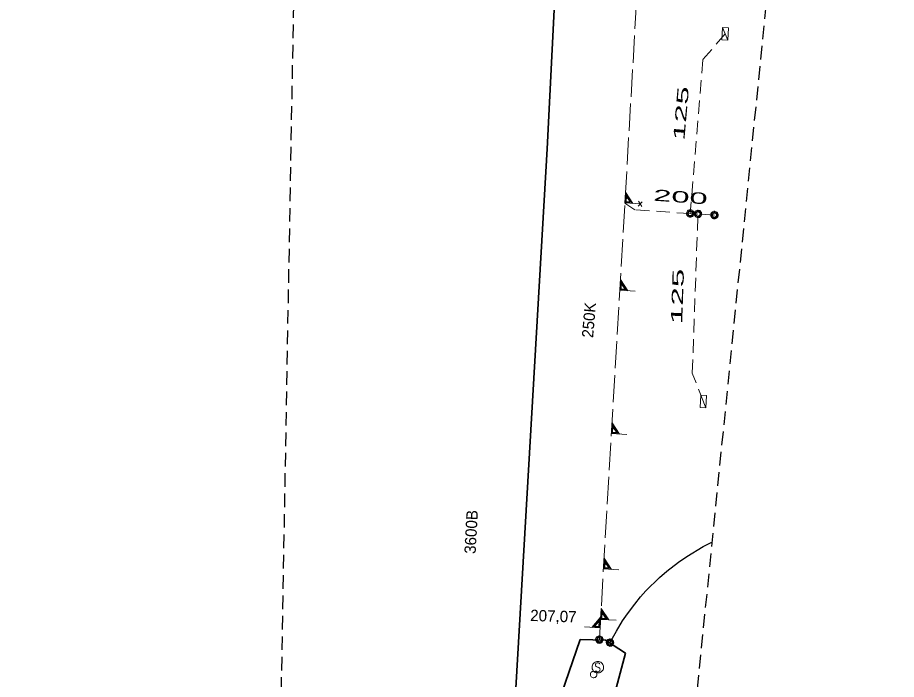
# Model space of a CAD drawing. Extents: x -744446 to -743929, y -1041261 to -1040599.
# Drawn here: x -744445.1 to -744383.1, y -1040917.5 to -1040870.7 of the extents above; entities that cross this region are included whole.
import ezdxf

# ---------------------------------------------------------------- set-up
doc = ezdxf.new("R2010")
doc.units = 0
doc.header["$LTSCALE"] = 0.32
doc.linetypes.add('LONG_DASHED', pattern=[7.5, 6, -1.5])
doc.linetypes.add('MEDIUM_DASHED', pattern=[4.5, 3, -1.5])
for name, color, linetype, lineweight in [('1', 7, 'MEDIUM_DASHED', 25), ('18', 7, 'Continuous', 13), ('20', 7, 'LONG_DASHED', 13), ('49', 7, 'MEDIUM_DASHED', 13)]:
    doc.layers.add(name, color=color, linetype=linetype, lineweight=lineweight)

msp = doc.modelspace()

# ---------------------------------------------------------------- linework, layer by layer
at = {"layer": '1'}
msp.add_lwpolyline([(-744438.077, -1041259.731), (-744438.679, -1041250.888), (-744445.125, -1041198.426), (-744434.434, -1041080.103), (-744426.87, -1040938.41), (-744425.446, -1040859.072), (-744414.192, -1040822.094), (-744390.076, -1040771.45), (-744357.118, -1040726.434), (-744307.278, -1040693.475), (-744241.36, -1040670.967), (-743937.498, -1040598.618), (-743928.655, -1040619.519), (-744129.684, -1040665.585), (-744218.109, -1040687.29), (-744311.358, -1040718.641), (-744361.198, -1040777.323), (-744391.745, -1040864.141), (-744411.355, -1041059.185), (-744416.379, -1041145.154), (-744432.569, -1041193.163), (-744432.047, -1041202.053), (-744422.803, -1041230.992), (-744424.813, -1041260.936)], close=True, dxfattribs=at)
at = {"layer": '18'}
for p, q in [((-744395.376, -1040871.437), (-744395.011, -1040872.332)), ((-744401.045, -1040883.732), (-744401.334, -1040884.051)), ((-744401.077, -1040884.069), (-744401.299, -1040883.684)), ((-744396.919, -1040897.398), (-744396.549, -1040898.291))]:
    msp.add_line(p, q, dxfattribs=at)
for points in [[(-744394.965, -1040871.455), (-744395.011, -1040872.328), (-744395.422, -1040872.306), (-744395.376, -1040871.433)], [(-744397.393, -1040884.557), (-744397.399, -1040884.501), (-744397.416, -1040884.448), (-744397.445, -1040884.399), (-744397.483, -1040884.358), (-744397.529, -1040884.326), (-744397.581, -1040884.304), (-744397.636, -1040884.293), (-744397.692, -1040884.295), (-744397.747, -1040884.308), (-744397.798, -1040884.333), (-744397.842, -1040884.368), (-744397.878, -1040884.411), (-744397.903, -1040884.461), (-744397.918, -1040884.516), (-744397.921, -1040884.572), (-744397.912, -1040884.627), (-744397.891, -1040884.68), (-744397.86, -1040884.726), (-744397.82, -1040884.765), (-744397.772, -1040884.795), (-744397.719, -1040884.814), (-744397.663, -1040884.821), (-744397.607, -1040884.817), (-744397.553, -1040884.8), (-744397.504, -1040884.773), (-744397.462, -1040884.735), (-744397.429, -1040884.69), (-744397.406, -1040884.639), (-744397.394, -1040884.584)], [(-744397.452, -1040884.56), (-744397.458, -1040884.511), (-744397.476, -1040884.465), (-744397.504, -1040884.424), (-744397.541, -1040884.391), (-744397.585, -1040884.369), (-744397.633, -1040884.357), (-744397.682, -1040884.357), (-744397.73, -1040884.369), (-744397.774, -1040884.392), (-744397.811, -1040884.425), (-744397.839, -1040884.466), (-744397.856, -1040884.513), (-744397.862, -1040884.562), (-744397.855, -1040884.611), (-744397.837, -1040884.657), (-744397.809, -1040884.697), (-744397.772, -1040884.73), (-744397.728, -1040884.752), (-744397.679, -1040884.764), (-744397.63, -1040884.763), (-744397.582, -1040884.751), (-744397.539, -1040884.727), (-744397.502, -1040884.694), (-744397.474, -1040884.653), (-744397.458, -1040884.606)], [(-744397.511, -1040884.564), (-744397.517, -1040884.522), (-744397.534, -1040884.484), (-744397.562, -1040884.453), (-744397.597, -1040884.43), (-744397.637, -1040884.419), (-744397.679, -1040884.419), (-744397.719, -1040884.431), (-744397.754, -1040884.454), (-744397.781, -1040884.486), (-744397.798, -1040884.524), (-744397.803, -1040884.565), (-744397.797, -1040884.607), (-744397.779, -1040884.644), (-744397.751, -1040884.676), (-744397.715, -1040884.698), (-744397.675, -1040884.709), (-744397.633, -1040884.708), (-744397.593, -1040884.695), (-744397.559, -1040884.672), (-744397.532, -1040884.639), (-744397.516, -1040884.601)], [(-744396.852, -1040884.593), (-744396.858, -1040884.537), (-744396.875, -1040884.484), (-744396.904, -1040884.435), (-744396.942, -1040884.394), (-744396.988, -1040884.362), (-744397.04, -1040884.34), (-744397.095, -1040884.329), (-744397.151, -1040884.331), (-744397.206, -1040884.344), (-744397.257, -1040884.369), (-744397.301, -1040884.404), (-744397.337, -1040884.447), (-744397.362, -1040884.497), (-744397.377, -1040884.552), (-744397.38, -1040884.608), (-744397.371, -1040884.663), (-744397.35, -1040884.716), (-744397.319, -1040884.762), (-744397.279, -1040884.801), (-744397.231, -1040884.831), (-744397.178, -1040884.85), (-744397.122, -1040884.857), (-744397.066, -1040884.853), (-744397.012, -1040884.836), (-744396.963, -1040884.809), (-744396.921, -1040884.771), (-744396.888, -1040884.726), (-744396.865, -1040884.675), (-744396.853, -1040884.62)], [(-744396.911, -1040884.596), (-744396.917, -1040884.547), (-744396.935, -1040884.501), (-744396.963, -1040884.46), (-744397, -1040884.427), (-744397.044, -1040884.405), (-744397.092, -1040884.393), (-744397.141, -1040884.393), (-744397.189, -1040884.405), (-744397.233, -1040884.428), (-744397.27, -1040884.461), (-744397.298, -1040884.502), (-744397.315, -1040884.549), (-744397.321, -1040884.598), (-744397.314, -1040884.647), (-744397.296, -1040884.693), (-744397.268, -1040884.733), (-744397.231, -1040884.766), (-744397.187, -1040884.788), (-744397.138, -1040884.8), (-744397.089, -1040884.799), (-744397.041, -1040884.787), (-744396.998, -1040884.763), (-744396.961, -1040884.73), (-744396.933, -1040884.689), (-744396.917, -1040884.642)], [(-744396.97, -1040884.6), (-744396.976, -1040884.558), (-744396.993, -1040884.52), (-744397.021, -1040884.489), (-744397.056, -1040884.466), (-744397.096, -1040884.455), (-744397.138, -1040884.455), (-744397.178, -1040884.467), (-744397.213, -1040884.49), (-744397.24, -1040884.522), (-744397.257, -1040884.56), (-744397.262, -1040884.601), (-744397.256, -1040884.643), (-744397.238, -1040884.68), (-744397.21, -1040884.712), (-744397.174, -1040884.734), (-744397.134, -1040884.745), (-744397.092, -1040884.744), (-744397.052, -1040884.731), (-744397.018, -1040884.708), (-744396.991, -1040884.675), (-744396.975, -1040884.637)], [(-744395.685, -1040884.671), (-744395.691, -1040884.615), (-744395.708, -1040884.562), (-744395.737, -1040884.513), (-744395.775, -1040884.472), (-744395.821, -1040884.44), (-744395.873, -1040884.418), (-744395.928, -1040884.407), (-744395.984, -1040884.409), (-744396.039, -1040884.422), (-744396.09, -1040884.447), (-744396.134, -1040884.482), (-744396.17, -1040884.525), (-744396.195, -1040884.575), (-744396.21, -1040884.63), (-744396.213, -1040884.686), (-744396.204, -1040884.741), (-744396.183, -1040884.794), (-744396.152, -1040884.84), (-744396.112, -1040884.879), (-744396.064, -1040884.909), (-744396.011, -1040884.928), (-744395.955, -1040884.935), (-744395.899, -1040884.931), (-744395.845, -1040884.914), (-744395.796, -1040884.887), (-744395.754, -1040884.849), (-744395.721, -1040884.804), (-744395.698, -1040884.753), (-744395.686, -1040884.698)], [(-744395.744, -1040884.674), (-744395.75, -1040884.625), (-744395.768, -1040884.579), (-744395.796, -1040884.538), (-744395.833, -1040884.505), (-744395.877, -1040884.483), (-744395.925, -1040884.471), (-744395.974, -1040884.471), (-744396.022, -1040884.483), (-744396.066, -1040884.506), (-744396.103, -1040884.539), (-744396.131, -1040884.58), (-744396.148, -1040884.627), (-744396.154, -1040884.676), (-744396.147, -1040884.725), (-744396.129, -1040884.771), (-744396.101, -1040884.811), (-744396.064, -1040884.844), (-744396.02, -1040884.866), (-744395.971, -1040884.878), (-744395.922, -1040884.877), (-744395.874, -1040884.865), (-744395.831, -1040884.841), (-744395.794, -1040884.808), (-744395.766, -1040884.767), (-744395.75, -1040884.72)], [(-744395.803, -1040884.678), (-744395.809, -1040884.636), (-744395.826, -1040884.598), (-744395.854, -1040884.567), (-744395.889, -1040884.544), (-744395.929, -1040884.533), (-744395.971, -1040884.533), (-744396.011, -1040884.545), (-744396.046, -1040884.568), (-744396.073, -1040884.6), (-744396.09, -1040884.638), (-744396.095, -1040884.679), (-744396.089, -1040884.721), (-744396.071, -1040884.758), (-744396.043, -1040884.79), (-744396.007, -1040884.812), (-744395.967, -1040884.823), (-744395.925, -1040884.822), (-744395.885, -1040884.809), (-744395.851, -1040884.786), (-744395.824, -1040884.753), (-744395.808, -1040884.715)], [(-744396.507, -1040897.414), (-744396.548, -1040898.287), (-744396.96, -1040898.267), (-744396.919, -1040897.394)], [(-744403.808, -1040914.643), (-744403.814, -1040914.587), (-744403.831, -1040914.534), (-744403.86, -1040914.485), (-744403.898, -1040914.444), (-744403.944, -1040914.412), (-744403.996, -1040914.39), (-744404.051, -1040914.379), (-744404.107, -1040914.381), (-744404.162, -1040914.394), (-744404.213, -1040914.419), (-744404.257, -1040914.454), (-744404.293, -1040914.497), (-744404.318, -1040914.547), (-744404.333, -1040914.602), (-744404.336, -1040914.658), (-744404.327, -1040914.713), (-744404.306, -1040914.766), (-744404.275, -1040914.812), (-744404.235, -1040914.851), (-744404.187, -1040914.881), (-744404.134, -1040914.9), (-744404.078, -1040914.907), (-744404.022, -1040914.903), (-744403.968, -1040914.886), (-744403.919, -1040914.859), (-744403.877, -1040914.821), (-744403.844, -1040914.776), (-744403.821, -1040914.725), (-744403.809, -1040914.67)], [(-744403.867, -1040914.646), (-744403.873, -1040914.597), (-744403.891, -1040914.551), (-744403.919, -1040914.51), (-744403.956, -1040914.477), (-744404, -1040914.455), (-744404.048, -1040914.443), (-744404.097, -1040914.443), (-744404.145, -1040914.455), (-744404.189, -1040914.478), (-744404.226, -1040914.511), (-744404.254, -1040914.552), (-744404.271, -1040914.599), (-744404.277, -1040914.648), (-744404.27, -1040914.697), (-744404.252, -1040914.743), (-744404.224, -1040914.783), (-744404.187, -1040914.816), (-744404.143, -1040914.838), (-744404.094, -1040914.85), (-744404.045, -1040914.849), (-744403.997, -1040914.837), (-744403.954, -1040914.813), (-744403.917, -1040914.78), (-744403.889, -1040914.739), (-744403.873, -1040914.692)], [(-744403.926, -1040914.65), (-744403.932, -1040914.608), (-744403.949, -1040914.57), (-744403.977, -1040914.539), (-744404.012, -1040914.516), (-744404.052, -1040914.505), (-744404.094, -1040914.505), (-744404.134, -1040914.517), (-744404.169, -1040914.54), (-744404.196, -1040914.572), (-744404.213, -1040914.61), (-744404.218, -1040914.651), (-744404.212, -1040914.693), (-744404.194, -1040914.73), (-744404.166, -1040914.762), (-744404.13, -1040914.784), (-744404.09, -1040914.795), (-744404.048, -1040914.794), (-744404.008, -1040914.781), (-744403.974, -1040914.758), (-744403.947, -1040914.725), (-744403.931, -1040914.687)], [(-744403.058, -1040914.852), (-744403.064, -1040914.796), (-744403.081, -1040914.743), (-744403.11, -1040914.694), (-744403.148, -1040914.653), (-744403.194, -1040914.621), (-744403.246, -1040914.599), (-744403.301, -1040914.588), (-744403.357, -1040914.59), (-744403.412, -1040914.603), (-744403.463, -1040914.628), (-744403.507, -1040914.663), (-744403.543, -1040914.706), (-744403.568, -1040914.756), (-744403.583, -1040914.811), (-744403.586, -1040914.867), (-744403.577, -1040914.922), (-744403.556, -1040914.975), (-744403.525, -1040915.021), (-744403.485, -1040915.06), (-744403.437, -1040915.09), (-744403.384, -1040915.109), (-744403.328, -1040915.116), (-744403.272, -1040915.112), (-744403.218, -1040915.095), (-744403.169, -1040915.068), (-744403.127, -1040915.03), (-744403.094, -1040914.985), (-744403.071, -1040914.934), (-744403.059, -1040914.879)], [(-744403.117, -1040914.855), (-744403.123, -1040914.806), (-744403.141, -1040914.76), (-744403.169, -1040914.719), (-744403.206, -1040914.686), (-744403.25, -1040914.664), (-744403.298, -1040914.652), (-744403.347, -1040914.652), (-744403.395, -1040914.664), (-744403.439, -1040914.687), (-744403.476, -1040914.72), (-744403.504, -1040914.761), (-744403.521, -1040914.808), (-744403.527, -1040914.857), (-744403.52, -1040914.906), (-744403.502, -1040914.952), (-744403.474, -1040914.992), (-744403.437, -1040915.025), (-744403.393, -1040915.047), (-744403.344, -1040915.059), (-744403.295, -1040915.058), (-744403.247, -1040915.046), (-744403.204, -1040915.022), (-744403.167, -1040914.989), (-744403.139, -1040914.948), (-744403.123, -1040914.901)], [(-744403.176, -1040914.859), (-744403.182, -1040914.817), (-744403.199, -1040914.779), (-744403.227, -1040914.748), (-744403.262, -1040914.725), (-744403.302, -1040914.714), (-744403.344, -1040914.714), (-744403.384, -1040914.726), (-744403.419, -1040914.749), (-744403.446, -1040914.781), (-744403.463, -1040914.819), (-744403.468, -1040914.86), (-744403.462, -1040914.902), (-744403.444, -1040914.939), (-744403.416, -1040914.971), (-744403.38, -1040914.993), (-744403.34, -1040915.004), (-744403.298, -1040915.003), (-744403.258, -1040914.99), (-744403.224, -1040914.967), (-744403.197, -1040914.934), (-744403.181, -1040914.896)], [(-744403.776, -1040916.592), (-744403.782, -1040916.523), (-744403.8, -1040916.456), (-744403.829, -1040916.392), (-744403.869, -1040916.335), (-744403.918, -1040916.285), (-744403.974, -1040916.244), (-744404.037, -1040916.214), (-744404.104, -1040916.194), (-744404.173, -1040916.187), (-744404.243, -1040916.191), (-744404.31, -1040916.207), (-744404.374, -1040916.235), (-744404.433, -1040916.273), (-744404.484, -1040916.321), (-744404.526, -1040916.376), (-744404.558, -1040916.438), (-744404.579, -1040916.505), (-744404.588, -1040916.574), (-744404.585, -1040916.644), (-744404.57, -1040916.712), (-744404.544, -1040916.776), (-744404.507, -1040916.836), (-744404.461, -1040916.888), (-744404.406, -1040916.931), (-744404.345, -1040916.964), (-744404.279, -1040916.987), (-744404.21, -1040916.997), (-744404.14, -1040916.996), (-744404.072, -1040916.983), (-744404.006, -1040916.958), (-744403.946, -1040916.923), (-744403.893, -1040916.877), (-744403.849, -1040916.824), (-744403.814, -1040916.763), (-744403.79, -1040916.698), (-744403.778, -1040916.629)], [(-744404.245, -1040917.106), (-744404.252, -1040917.054), (-744404.269, -1040917.004), (-744404.298, -1040916.96), (-744404.336, -1040916.923), (-744404.38, -1040916.896), (-744404.431, -1040916.88), (-744404.483, -1040916.875), (-744404.534, -1040916.882), (-744404.583, -1040916.901), (-744404.627, -1040916.931), (-744404.663, -1040916.97), (-744404.689, -1040917.015), (-744404.703, -1040917.066), (-744404.706, -1040917.118), (-744404.698, -1040917.17), (-744404.678, -1040917.218), (-744404.647, -1040917.261), (-744404.608, -1040917.296), (-744404.561, -1040917.32), (-744404.511, -1040917.334), (-744404.458, -1040917.336), (-744404.407, -1040917.326), (-744404.358, -1040917.304), (-744404.316, -1040917.272), (-744404.284, -1040917.232), (-744404.26, -1040917.185), (-744404.247, -1040917.134)]]:
    msp.add_lwpolyline(points, close=True, dxfattribs=at)
for points in [[(-744401.184, -1040883.884), (-744402.277, -1040883.82), (-744402.232, -1040883.052), (-744401.7, -1040883.854)], [(-744401.816, -1040883.797), (-744402.23, -1040883.773), (-744402.197, -1040883.208), (-744401.814, -1040883.797)], [(-744401.896, -1040883.745), (-744402.187, -1040883.728), (-744402.166, -1040883.357), (-744401.896, -1040883.746)], [(-744401.541, -1040890.049), (-744402.635, -1040889.985), (-744402.59, -1040889.217), (-744402.058, -1040890.019)], [(-744402.173, -1040889.962), (-744402.588, -1040889.938), (-744402.555, -1040889.373), (-744402.172, -1040889.962)], [(-744402.254, -1040889.911), (-744402.545, -1040889.894), (-744402.523, -1040889.522), (-744402.254, -1040889.912)], [(-744402.13, -1040900.161), (-744403.224, -1040900.097), (-744403.179, -1040899.329), (-744402.647, -1040900.131)], [(-744402.762, -1040900.074), (-744403.177, -1040900.05), (-744403.144, -1040899.485), (-744402.761, -1040900.074)], [(-744402.843, -1040900.023), (-744403.134, -1040900.006), (-744403.112, -1040899.634), (-744402.843, -1040900.024)], [(-744402.687, -1040909.715), (-744403.781, -1040909.651), (-744403.736, -1040908.883), (-744403.204, -1040909.685)], [(-744403.319, -1040909.628), (-744403.734, -1040909.604), (-744403.701, -1040909.039), (-744403.318, -1040909.628)], [(-744403.4, -1040909.577), (-744403.691, -1040909.56), (-744403.669, -1040909.188), (-744403.4, -1040909.578)], [(-744402.895, -1040913.279), (-744403.989, -1040913.215), (-744403.944, -1040912.447), (-744403.412, -1040913.249)], [(-744403.527, -1040913.192), (-744403.942, -1040913.168), (-744403.909, -1040912.603), (-744403.526, -1040913.192)], [(-744403.608, -1040913.141), (-744403.899, -1040913.124), (-744403.877, -1040912.752), (-744403.608, -1040913.142)], [(-744405.114, -1040913.747), (-744404.02, -1040913.811), (-744403.975, -1040913.041), (-744404.597, -1040913.777)], [(-744404.476, -1040913.733), (-744404.061, -1040913.757), (-744404.028, -1040913.193), (-744404.477, -1040913.733)], [(-744404.389, -1040913.691), (-744404.099, -1040913.708), (-744404.077, -1040913.338), (-744404.389, -1040913.692)], [(-744404.031, -1040916.369), (-744404.053, -1040916.331), (-744404.085, -1040916.301), (-744404.123, -1040916.28), (-744404.166, -1040916.27), (-744404.21, -1040916.272), (-744404.251, -1040916.286), (-744404.287, -1040916.311), (-744404.316, -1040916.344), (-744404.334, -1040916.384), (-744404.34, -1040916.428), (-744404.335, -1040916.471), (-744404.318, -1040916.512), (-744404.291, -1040916.546), (-744404.256, -1040916.572), (-744404.215, -1040916.587), (-744404.171, -1040916.591), (-744404.167, -1040916.591)], [(-744404.332, -1040916.822), (-744404.308, -1040916.859), (-744404.275, -1040916.888), (-744404.235, -1040916.907), (-744404.192, -1040916.915), (-744404.148, -1040916.91), (-744404.107, -1040916.894), (-744404.072, -1040916.868), (-744404.045, -1040916.833), (-744404.028, -1040916.793), (-744404.023, -1040916.749), (-744404.03, -1040916.705), (-744404.048, -1040916.665), (-744404.077, -1040916.632), (-744404.113, -1040916.607), (-744404.155, -1040916.593), (-744404.172, -1040916.591)]]:
    msp.add_lwpolyline(points, dxfattribs=at)
at = {"layer": '18', "lineweight": 35}
msp.add_lwpolyline([(-744405.436, -1040914.627), (-744403.633, -1040914.677), (-744402.237, -1040915.595), (-744403.265, -1040919.486), (-744405.096, -1040919.552), (-744406.737, -1040918.467)], close=True, dxfattribs=at)
at = {"layer": '20'}
msp.add_line((-744404.072, -1040914.656), (-744401.298, -1040867.055), dxfattribs=at)
at = {"layer": '20', "linetype": 'Continuous', "lineweight": 35}
msp.add_lwpolyline([(-744429.62, -1041252.21), (-744428.789, -1041237.94), (-744437.959, -1041195.193), (-744423.3, -1041145.69), (-744417.879, -1041053.98), (-744409.949, -1040917.67), (-744407.76, -1040880.01), (-744407.219, -1040869.23), (-744404.395, -1040847.829), (-744400.25, -1040827.35), (-744393.491, -1040807.621), (-744384.879, -1040787.9), (-744372.238, -1040768.547), (-744361.26, -1040752.62), (-744345.317, -1040736.555), (-744330.739, -1040723.14), (-744312.333, -1040710.859), (-744294.67, -1040700.75), (-744274.728, -1040692.583), (-744254.699, -1040686.49), (-744133.87, -1040657.39), (-743953.289, -1040613.85), (-743946.017, -1040612.141)], dxfattribs=at)
at = {"layer": '20', "lineweight": 25}
msp.add_lwpolyline([(-744403.322, -1040914.865), (-744402.873, -1040914.034), (-744402.431, -1040913.318), (-744402.087, -1040912.814), (-744401.574, -1040912.137), (-744401.162, -1040911.629), (-744400.785, -1040911.198), (-744399.84, -1040910.254), (-744399.3, -1040909.807), (-744398.495, -1040909.183), (-744397.908, -1040908.765), (-744396.745, -1040908.076), (-744396.14, -1040907.765), (-744396.131, -1040907.761)], dxfattribs=at)
at = {"layer": '49'}
for points in [[(-744395.19, -1040871.89), (-744396.763, -1040873.705), (-744397.657, -1040884.57)], [(-744397.657, -1040884.57), (-744401.565, -1040884.307), (-744402.276, -1040883.826)], [(-744395.949, -1040884.684), (-744397.116, -1040884.606), (-744397.657, -1040884.57)], [(-744396.73, -1040897.85), (-744397.515, -1040895.83), (-744397.116, -1040884.606)]]:
    msp.add_lwpolyline(points, dxfattribs=at)

# ---------------------------------------------------------------- texts
at = {"layer": '1'}
for s, rotation, width, p in [('125 ', 85, 2.15, (-744398.078, -1040879.447)), ('200 ', 356, 2.15, (-744400.289, -1040883.654)), ('125 ', 88, 2.2, (-744398.234, -1040892.396))]:
    msp.add_text(s, height=0.8, rotation=rotation, dxfattribs=dict(at, width=width)).set_placement(p)
for s, rotation, p in [('250K', 85, (-744404.517, -1040893.365)), ('3600B ', 87, (-744412.804, -1040908.604)), ('207,07', 358, (-744408.963, -1040913.322))]:
    msp.add_text(s, height=0.8, rotation=rotation, dxfattribs=at).set_placement(p)

doc.saveas('drawing.dxf')
